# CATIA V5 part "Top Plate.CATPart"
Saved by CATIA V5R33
Part number: Top Plate
Bounding box of the stored display mesh (mm): x -125 to 125, y 0 to 150, z 180 to 210
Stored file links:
  D:\PROJECTS\Project 2023\CATIA V5 6R 2023\Resources\Tutorial Files\c12_catia_v5_6r2023_tut\c12tut2\Top Plate.CATPart
  E:\_Deepak\2017_Deepak\CATIA\Resources\Tutorial Files\Tutorials\c12_catia_v5_6r2015_tut\c12tut2\Top Plate_cat_v5-6r2016.CATPart
  D:\PROJECTS\Project 2023\CATIA V5 6R 2023\Resources\Tutorial Files\c12_catia_v5_6r2023_tut\c12tut2\Bush.CATPart
  D:\PROJECTS\Project 2023\CATIA V5 6R 2023\Resources\Tutorial Files\c12_catia_v5_6r2023_tut\c12tut2\Bottom Plate.CATPart
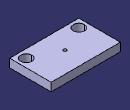
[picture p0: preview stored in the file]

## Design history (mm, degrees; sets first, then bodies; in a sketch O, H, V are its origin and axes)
Set1
  DatumSurface1: linked copy from another document
  DatumCurve1 to DatumCurve5: linked copy from another document
Body1 (main body)
  Sketch1 on face of DatumSurface1, origin (0, 0, 210), H (1, 0, 0), V (0, 1, 0)
    projected line E1 (-125, 0) -> (125, 0) from edge of DatumCurve1
    point P1 (-125, 0)
    point P2 (125, 0)
    projected line E2 (125, 0) -> (125, 150) from edge of DatumCurve2
    point P3 (125, 0)
    point P4 (125, 150)
    projected line E3 (125, 150) -> (-125, 150) from edge of DatumCurve3
    point P5 (125, 150)
    point P6 (-125, 150)
    projected line E4 (-125, 150) -> (-125, 0) from edge of DatumCurve4
    point P7 (-125, 150)
    point P8 (-125, 0)
    projected circle E5 centre (95, 30) radius 20 from edge of DatumCurve5
    circle A1 centre (-95, 30) radius 20
    symmetry: E5 A1 V
    coincidence: P1 P8, P2 P3, P4 P5, P6 P7
  Pad1: profile Sketch1, direction (0, 0, -1), length 30
  Sketch2 on face of Pad1, origin (0, 0, 210), H (1, 0, 0), V (0, 1, 0)
    circle A1 centre (0, 75) radius 6
    point P1 (0, 75)
    reference projected line E1 (-125, 0) -> (125, 0) from edge [face of Pad1 | face of Pad1]
    radius A1 = 6
    distance E1 P1 = 75
    coincidence: P1 V
  Pocket1: profile Sketch2, direction (0, 0, -1), through (limit type 6)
